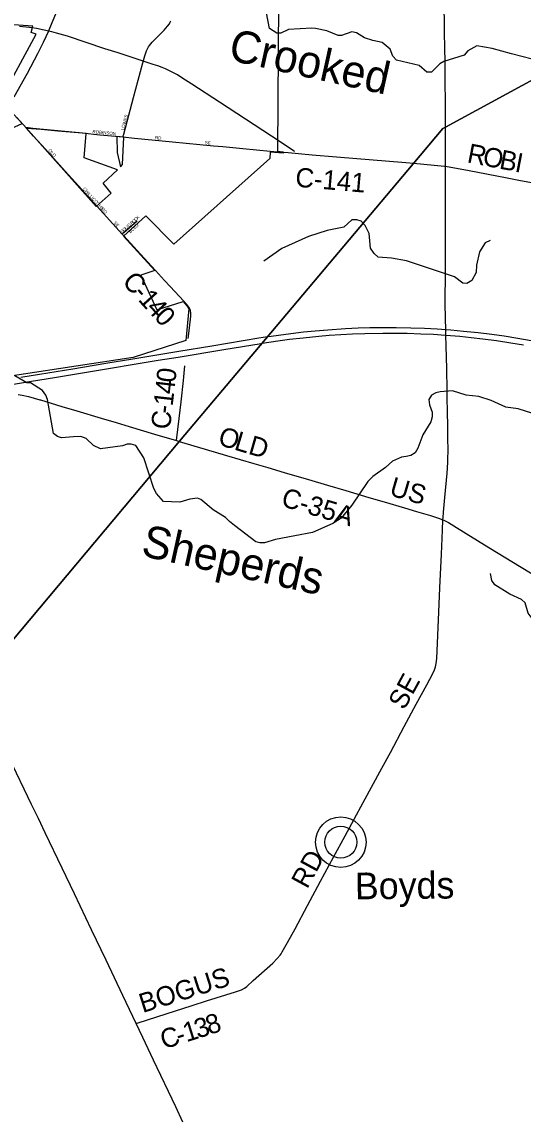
# Model space of a CAD drawing. Extents: x -51392 to 1635000, y 156707 to 696232.
# Drawn here: x 149662 to 157464, y 467379 to 484438 of the extents above; entities that cross this region are included whole.
import ezdxf

# ---------------------------------------------------------------- set-up
doc = ezdxf.new("R2010")
doc.units = 0
for name, color, linetype in [('GM_X_City_Street', 7, 'Continuous'), ('GM_X_City_Street_Text', 7, 'Continuous'), ('GM_X_Corporation', 7, 'Continuous'), ('GM_X_County_Road', 7, 'Continuous'), ('GM_X_County_Road_Text', 7, 'Continuous'), ('GM_X_Minor_River', 7, 'Continuous'), ('GM_X_Minor_River_Text', 7, 'Continuous'), ('GM_X_Rail_Line', 7, 'Continuous'), ('GM_X_State_Route', 7, 'Continuous'), ('GM_X_Township', 7, 'Continuous'), ('GM_X_Unincorporated', 7, 'Continuous'), ('GM_X_Unincorporated_Text', 7, 'Continuous'), ('GM_X_US_Route', 7, 'Continuous')]:
    doc.layers.add(name, color=color, linetype=linetype)

msp = doc.modelspace()

# ---------------------------------------------------------------- linework, layer by layer
at = {"layer": 'GM_X_City_Street'}
for points in [[(151234, 482647), (151246, 482692), (151400, 483261), (151542, 483800), (151573, 483910), (151601, 483986), (151623, 484030), (151635, 484050), (151649, 484070), (151692, 484120), (151875, 484307), (151929, 484369), (151958, 484409), (151972, 484432), (151982, 484452)], [(149733, 482785), (149576, 482957)], [(151223, 481136), (150786, 481618), (150545, 481885), (150336, 482115), (150029, 482456), (149843, 482662), (149733, 482785)], [(149733, 482785), (149960, 482769), (150222, 482744), (150598, 482709), (150876, 482682), (151121, 482658), (151234, 482647)], [(151234, 482647), (151416, 482630), (152004, 482573), (152642, 482511), (152790, 482497), (153100, 482468), (153527, 482427)], [(151223, 481136), (151251, 481161), (151456, 481341)], [(151248, 481108), (151223, 481136)]]:
    msp.add_lwpolyline(points, dxfattribs=at)
at = {"layer": 'GM_X_Corporation'}
for points in [[(153655, 484747), (153640, 482426), (153729, 482417), (153729, 482397), (153525, 482411), (153524, 482314), (152029, 480980), (151592, 481421), (151241, 481104), (151732, 480567), (151514, 480496), (151763, 479957), (152171, 480088), (152237, 480015), (152263, 479970), (152216, 479482), (151394, 479213), (148728, 478810)], [(149497, 482778), (149665, 482858), (149328, 483218), (149886, 484247), (149804, 484275), (149831, 484374), (149156, 484419)]]:
    msp.add_lwpolyline(points, dxfattribs=at)
for points in [[(150818, 481567), (151052, 481775), (150928, 481930), (151150, 482136), (150630, 482320), (150660, 482699), (149831, 482778), (149722, 482795)], [(151141, 482654), (151144, 482404), (151197, 482184), (151230, 482218), (151246, 482644)]]:
    msp.add_lwpolyline(points, close=True, dxfattribs=at)
at = {"layer": 'GM_X_County_Road'}
for points in [[(156258, 482801), (156256, 483038), (156254, 483235), (156252, 483465), (156251, 483792), (156248, 484055), (156243, 484252), (156242, 484416), (156237, 484662), (156235, 485006), (156237, 485268), (156238, 485482), (156253, 486219), (156258, 486646), (156261, 486941), (156265, 487269), (156269, 487942), (156274, 488352), (156274, 488647), (156276, 488876), (156278, 489122), (156282, 489351)], [(156259, 482193), (156259, 482628), (156258, 482801)], [(153527, 482427), (153644, 482418)], [(153644, 482418), (153806, 482404), (154183, 482371), (154559, 482340), (155640, 482248), (155760, 482237)], [(155760, 482237), (156239, 482195), (156259, 482193)], [(156216, 476690), (156218, 476726), (156225, 476810), (156248, 477038), (156280, 477414), (156286, 477495), (156292, 477594), (156297, 477808), (156295, 477923), (156294, 478021), (156293, 478136), (156288, 478382), (156282, 478578), (156281, 478709), (156275, 479037), (156267, 479398), (156263, 479563), (156262, 479592), (156261, 479650), (156260, 479699), (156258, 479774), (156253, 480102), (156254, 480512), (156254, 481054), (156256, 481398), (156257, 481775), (156259, 482193)], [(156259, 482193), (156626, 482124), (157190, 482017), (157399, 481977), (157655, 481926)], [(151739, 480568), (151508, 480822), (151248, 481108)], [(152182, 480091), (151971, 480318), (151881, 480414), (151739, 480568)], [(152252, 479513), (152266, 479628), (152291, 479858), (152292, 479907), (152287, 479940), (152276, 479971), (152260, 480000), (152229, 480039), (152182, 480091)], [(152068, 477921), (152109, 478265), (152139, 478527), (152175, 478855), (152199, 479085)], [(149601, 478640), (149666, 478631), (149762, 478608), (149939, 478557)], [(149939, 478557), (149952, 478554), (150281, 478454), (150517, 478383), (150894, 478271), (151130, 478202), (151334, 478140), (151727, 478023), (152068, 477921)], [(152068, 477921), (152112, 477908)], [(152112, 477908), (152516, 477790), (152847, 477692), (153271, 477566), (153492, 477503), (153744, 477428), (154121, 477316), (154420, 477228), (154703, 477144), (155065, 477037), (155301, 476967), (155616, 476875), (155803, 476820)], [(155803, 476820), (156025, 476755), (156150, 476714), (156216, 476690)], [(156210, 476530), (156216, 476690)], [(156216, 476690), (156229, 476685), (156274, 476662), (156301, 476647), (156387, 476595), (156580, 476476), (156933, 476259), (157435, 475951), (157938, 475645), (158247, 475455), (158540, 475277), (158737, 475157), (158989, 475003), (159252, 474840), (159612, 474610), (160173, 474235), (160648, 473917), (160960, 473705), (161095, 473605), (161153, 473560)], [(151441, 468852), (151471, 468862), (151909, 469001), (152315, 469132), (152534, 469201), (152987, 469345), (153081, 469377), (153125, 469399), (153165, 469429), (153262, 469518), (153568, 469791), (153638, 469861), (153680, 469912), (153698, 469937), (153716, 469967), (153797, 470110), (153914, 470326), (154109, 470687), (154308, 471064), (154512, 471439), (154692, 471770), (154974, 472289), (155265, 472822), (155398, 473067), (155615, 473472), (155801, 473819), (155967, 474121), (156059, 474295), (156086, 474355), (156102, 474402), (156113, 474451), (156120, 474533), (156153, 475254), (156169, 475631), (156194, 476155), (156210, 476530)]]:
    msp.add_lwpolyline(points, dxfattribs=at)
at = {"layer": 'GM_X_Minor_River'}
for points in [[(156982, 484022), (156742, 484064), (156603, 483988), (156547, 483922), (156233, 483821), (156168, 483785), (156038, 483655), (155966, 483657), (155844, 483758), (155496, 483843), (155436, 483903), (155393, 484014), (155273, 484116), (155127, 484147), (154997, 484189), (154870, 484270), (154798, 484284), (154635, 484225), (154583, 484225), (154408, 484301), (154234, 484336), (154174, 484342), (153813, 484321), (153695, 484262), (153631, 484262), (153517, 484336), (153470, 484579)], [(157853, 482036), (157915, 482182), (157937, 482313), (158023, 482517), (158085, 482707), (158162, 482857), (158232, 483052), (158352, 483592), (158356, 483655), (158350, 483763), (158304, 483825), (157972, 483925), (157914, 483928), (157794, 483854), (157734, 483836), (157608, 483858), (157286, 483940), (156982, 484022)], [(156953, 481038), (156876, 480998), (156785, 480862), (156738, 480654), (156732, 480538), (156667, 480412), (156589, 480366), (156525, 480372), (156395, 480473), (155650, 480719), (155416, 480760), (155208, 480779), (155146, 480835), (155090, 480915), (155067, 481146), (155008, 481272), (154944, 481339), (154874, 481359), (154798, 481359), (154736, 481301), (154672, 481241), (154415, 481194), (154121, 481099), (153706, 480910), (153427, 480714)], [(156966, 478547), (156774, 478608), (156576, 478627), (156366, 478696), (156174, 478682), (156104, 478666), (156040, 478630), (155996, 478564), (156005, 478478), (156049, 478364), (156051, 478292), (156028, 478212), (155903, 478014), (155828, 477802), (155782, 477730), (155718, 477690), (155642, 477676), (155572, 477666), (155432, 477603), (155321, 477501), (155124, 477363), (155046, 477283), (154796, 476919), (154634, 476714), (154501, 476630), (154184, 476491), (153910, 476439), (153608, 476384), (153437, 476333), (153367, 476329), (153305, 476345), (152970, 476603), (152893, 476663), (152829, 476723), (152639, 476846), (152448, 477007), (152396, 477025), (152278, 477011), (152119, 476966), (151993, 476970), (151865, 476975), (151756, 477097), (151716, 477179), (151560, 477655), (151435, 477847), (151361, 477864), (151303, 477866), (151226, 477838), (150886, 477793), (150774, 477846), (150661, 477954), (150581, 477984), (150463, 477981), (150280, 477967), (150214, 477986), (150155, 478032), (150061, 478559), (150035, 478629), (149981, 478700), (149796, 478822), (149740, 478823), (149552, 478931)], [(157603, 478351), (157387, 478416), (157195, 478440), (156966, 478547)], [(159910, 475124), (159729, 475069), (159601, 475011), (159487, 474999), (159295, 474883), (159185, 474877), (159051, 474793), (158961, 474731), (158685, 474738), (158261, 474818), (157847, 474957), (157777, 475001), (157709, 475073), (157649, 475137), (157591, 475174), (157545, 475238), (157497, 475398), (157439, 475450), (157257, 475531), (157022, 475675), (156980, 475743), (156958, 475856)]]:
    msp.add_lwpolyline(points, dxfattribs=at)
at = {"layer": 'GM_X_Rail_Line'}
for points in [[(153901, 482424), (153545, 482662), (152736, 483190), (152307, 483469), (152151, 483569), (152082, 483612), (151951, 483681), (151897, 483706), (151843, 483729), (151776, 483753), (151707, 483776), (151552, 483827), (151160, 483955), (150955, 484021), (150369, 484214), (150202, 484264), (150128, 484285), (149887, 484335), (149819, 484345), (149730, 484357), (149624, 484367)], [(153907, 482420), (153901, 482424)]]:
    msp.add_lwpolyline(points, dxfattribs=at)
at = {"layer": 'GM_X_State_Route'}
for points in [[(149539, 483270), (149748, 483642), (149911, 483945), (149998, 484121), (150040, 484212), (150075, 484291), (150135, 484428), (150207, 484601)], [(152169, 467315), (152057, 467553), (151712, 468279), (151544, 468635), (151441, 468852), (151234, 469286), (150974, 469835), (150747, 470308), (150480, 470871), (150288, 471270), (150025, 471818), (149920, 472040), (149812, 472261), (149463, 472985)]]:
    msp.add_lwpolyline(points, dxfattribs=at)
at = {"layer": 'GM_X_Township'}
for points in [[(163036, 495918), (164490, 494623), (164825, 494309), (165024, 494079), (165191, 493819), (165755, 492875), (166035, 492423), (166101, 492345), (166384, 492134), (166408, 492117), (168306, 492432), (170778, 490644), (166293, 488255), (156255, 482801), (156216, 482780), (155754, 482231), (153370, 479403), (152114, 477913), (148909, 474096)], [(148909, 474096), (152114, 477913), (153370, 479403), (155754, 482231), (156216, 482780), (156255, 482801), (166293, 488255), (170778, 490644)]]:
    msp.add_lwpolyline(points, dxfattribs=at)
at = {"layer": 'GM_X_Unincorporated'}
for radius in [393, 249]:
    msp.add_circle((154626, 471672), radius, dxfattribs=at)
at = {"layer": 'GM_X_US_Route'}
for points in [[(149467, 478790), (149779, 478841), (150200, 478910), (150669, 478988), (151785, 479172), (152093, 479222), (152805, 479340), (153388, 479435), (153401, 479437), (153647, 479475), (153826, 479499), (154038, 479523), (154283, 479548), (154446, 479562), (154626, 479573), (154807, 479583), (155003, 479590), (155282, 479596), (155463, 479596), (155660, 479593), (155873, 479586), (156069, 479576), (156250, 479564), (156263, 479563), (156479, 479546), (156658, 479528), (156837, 479507), (157049, 479479), (157276, 479445), (157470, 479413)], [(149643, 478907), (149935, 478955), (150452, 479041), (150970, 479127), (151391, 479195), (151763, 479257), (152103, 479313), (152621, 479398), (153349, 479519), (153487, 479540), (153544, 479549), (153771, 479580), (154048, 479613), (154228, 479631), (154424, 479646), (154702, 479664), (154898, 479675), (155079, 479680), (155308, 479683), (155489, 479683), (155718, 479678), (155931, 479670), (156128, 479660), (156261, 479650), (156340, 479644), (156536, 479627), (156765, 479603), (156976, 479577), (157171, 479551), (157382, 479517), (157591, 479480)]]:
    msp.add_lwpolyline(points, dxfattribs=at)

# ---------------------------------------------------------------- texts
at = {"layer": 'GM_X_City_Street_Text'}
for s, rotation, p in [('LOWES', 74.7577, (151249, 482746)), ('ROBINSON', 354.1105, (150758, 482708)), ('RD', 354.6355, (151732, 482612)), ('OLD', 311.356, (150067, 482435)), ('SE', 353.4051, (152507, 482536)), ('CHILLICOTHE', 312.0174, (150605, 481837)), ('RD', 313.4187, (150890, 481519)), ('K', 41.8754, (151463, 481361)), ('SE', 310.3477, (151086, 481309)), ('O', 41.3021, (151252, 481173)), ('L', 41.8622, (151286, 481203)), ('I', 41.8889, (151312, 481226)), ('D', 41.8581, (151328, 481241)), ('BLVD', 41.3002, (151349, 481147)), ('R', 41.8776, (151371, 481279)), ('O', 41.8581, (151401, 481306)), ('C', 41.8615, (151433, 481335)), ('S', 36.3208, (151220, 481149))]:
    msp.add_text(s, height=50, rotation=rotation, dxfattribs=at).set_placement(p)
at = {"layer": 'GM_X_County_Road_Text'}
for s, rotation, p in [('R', 349.0694, (156580, 482254)), ('O', 349.0679, (156822, 482207)), ('B', 349.0716, (157081, 482157)), ('I', 349.0648, (157323, 482110)), ('C-141', 355.0197, (153910, 481875)), ('C', 312.3299, (151209, 480385)), ('-', 312.3244, (151375, 480203)), ('1', 312.3303, (151458, 480111)), ('4', 312.3371, (151582, 479975)), ('0', 312.4065, (151707, 479838)), ('0', 83.8018, (152050, 478816)), ('4', 83.5821, (152029, 478633)), ('1', 83.4956, (152008, 478450)), ('C', 83.4919, (151967, 478086)), ('-', 83.4919, (151995, 478329)), ('O', 343.1139, (152699, 477862)), ('L', 343.1537, (152952, 477786)), ('D', 344.0415, (153172, 477719)), ('US', 343.7873, (155368, 477074)), ('C-35A', 343.5514, (153682, 476908)), ('SE', 61.3099, (155614, 473716)), ('RD', 61.5327, (154104, 470933)), ('BOGUS', 17.5674, (151542, 469012)), ('3', 17.6355, (152400, 468614)), ('8', 18.1563, (152579, 468671)), ('C', 17.4898, (151871, 468447)), ('1', 17.5268, (152223, 468558)), ('-', 17.4975, (152106, 468521))]:
    msp.add_text(s, height=300, rotation=rotation, dxfattribs=at).set_placement(p)
at = {"layer": 'GM_X_Minor_River_Text'}
for s, rotation, p in [('Crooked', 347.5472, (152859, 483849)), ('Sheperds', 347.5469, (151501, 476133))]:
    msp.add_text(s, height=500, rotation=rotation, dxfattribs=at).set_placement(p)
at = {"layer": 'GM_X_Unincorporated_Text'}
msp.add_text('Boyds', height=417, rotation=0.5386, dxfattribs=at).set_placement((154847, 470782))

doc.saveas('drawing.dxf')
